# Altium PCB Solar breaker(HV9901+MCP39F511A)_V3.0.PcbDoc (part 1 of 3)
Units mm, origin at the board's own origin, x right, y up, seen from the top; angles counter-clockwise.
Board outline 92.89 x 56.75 mm, 4 copper layers (Component Side, Layer 2, Layer 3, Solder Side), stack 0.466 mm thick; 133 components, 95 nets, 366 pads, 141 vias.
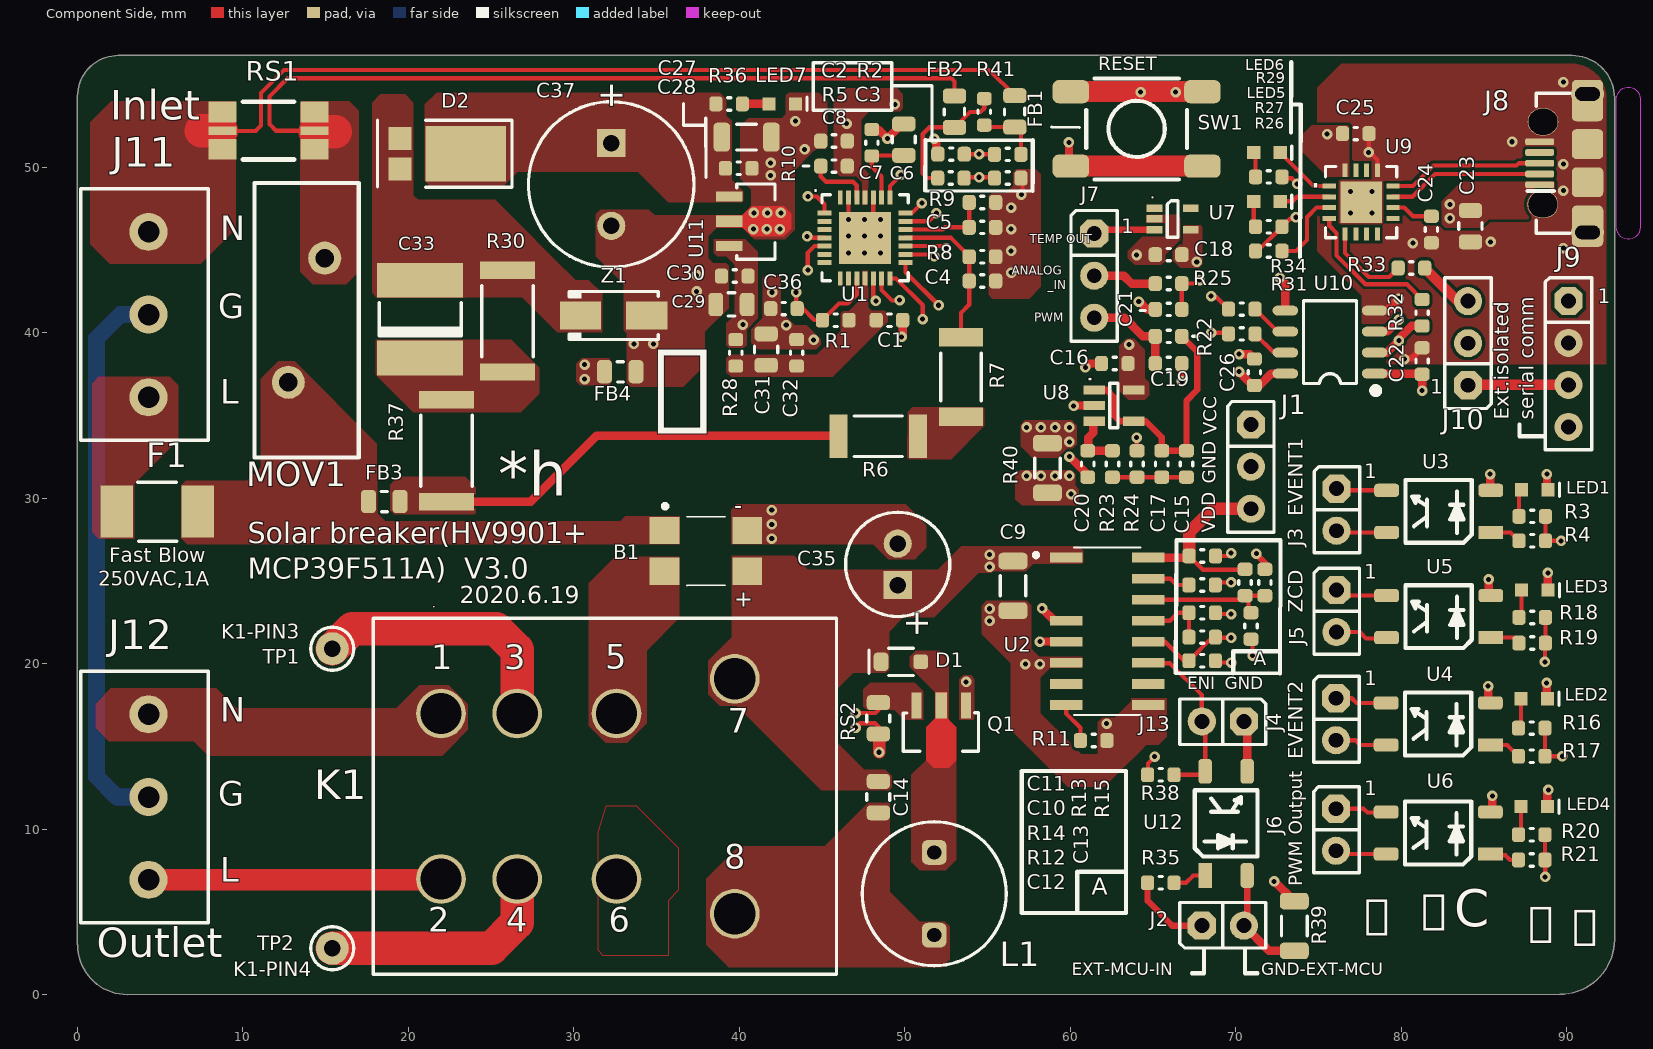
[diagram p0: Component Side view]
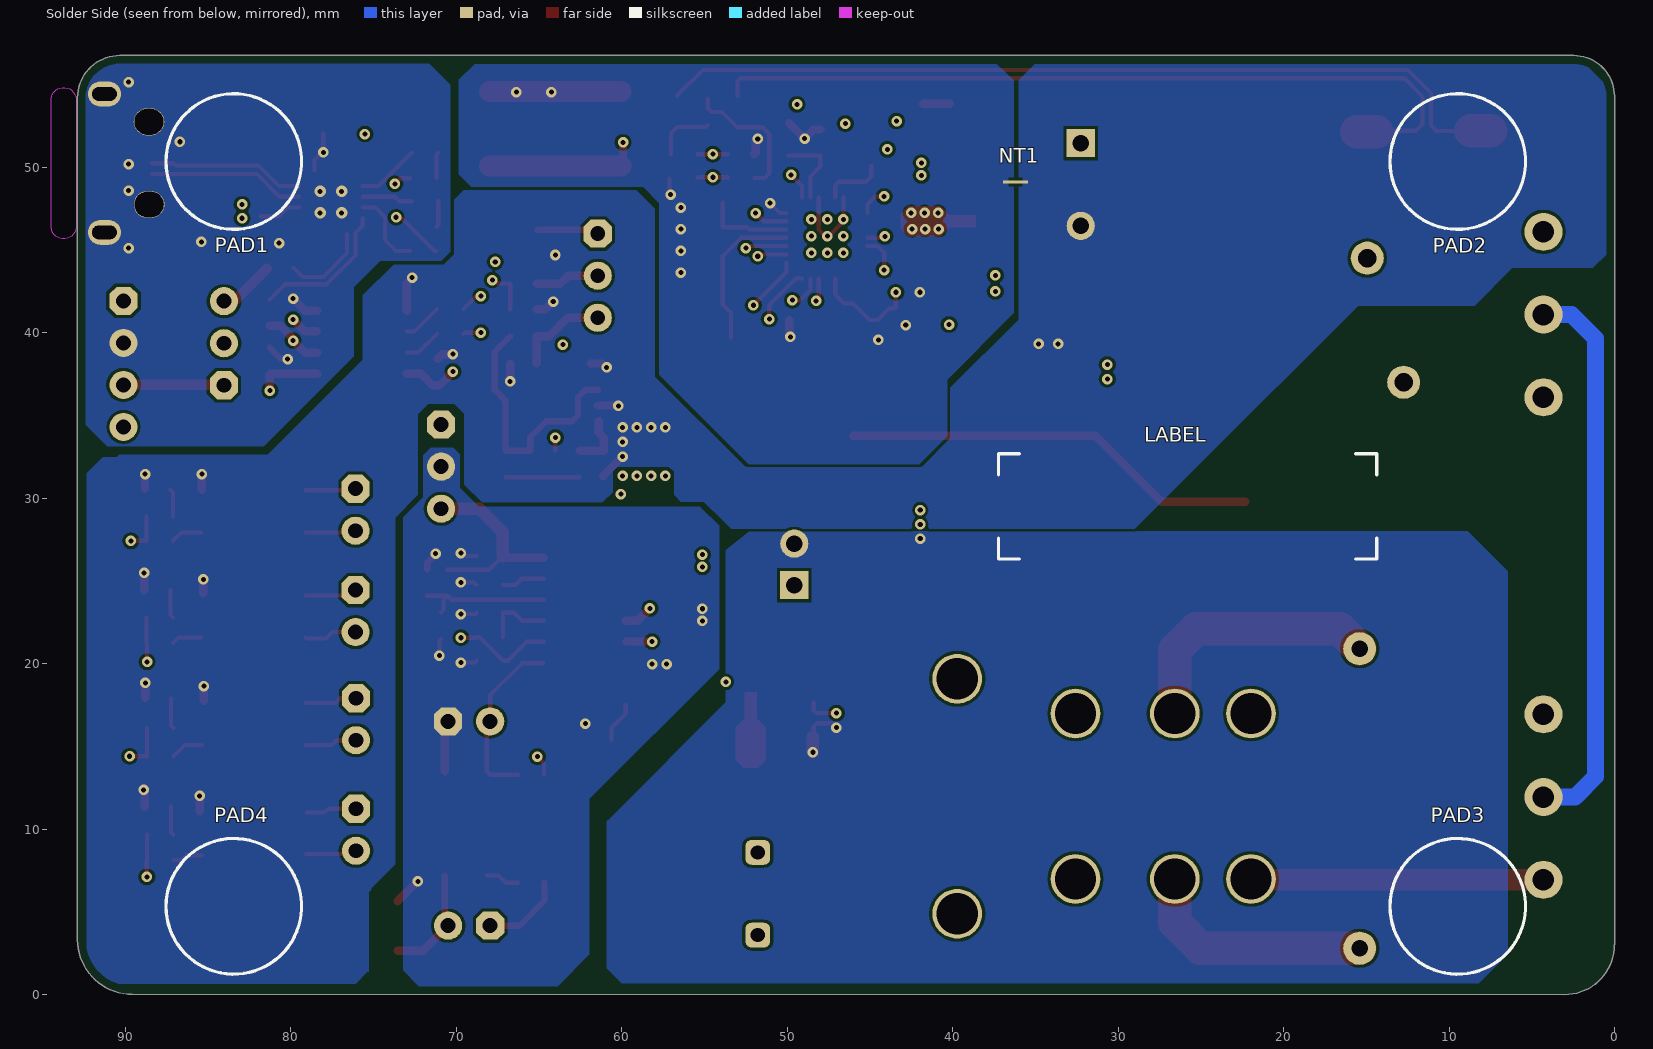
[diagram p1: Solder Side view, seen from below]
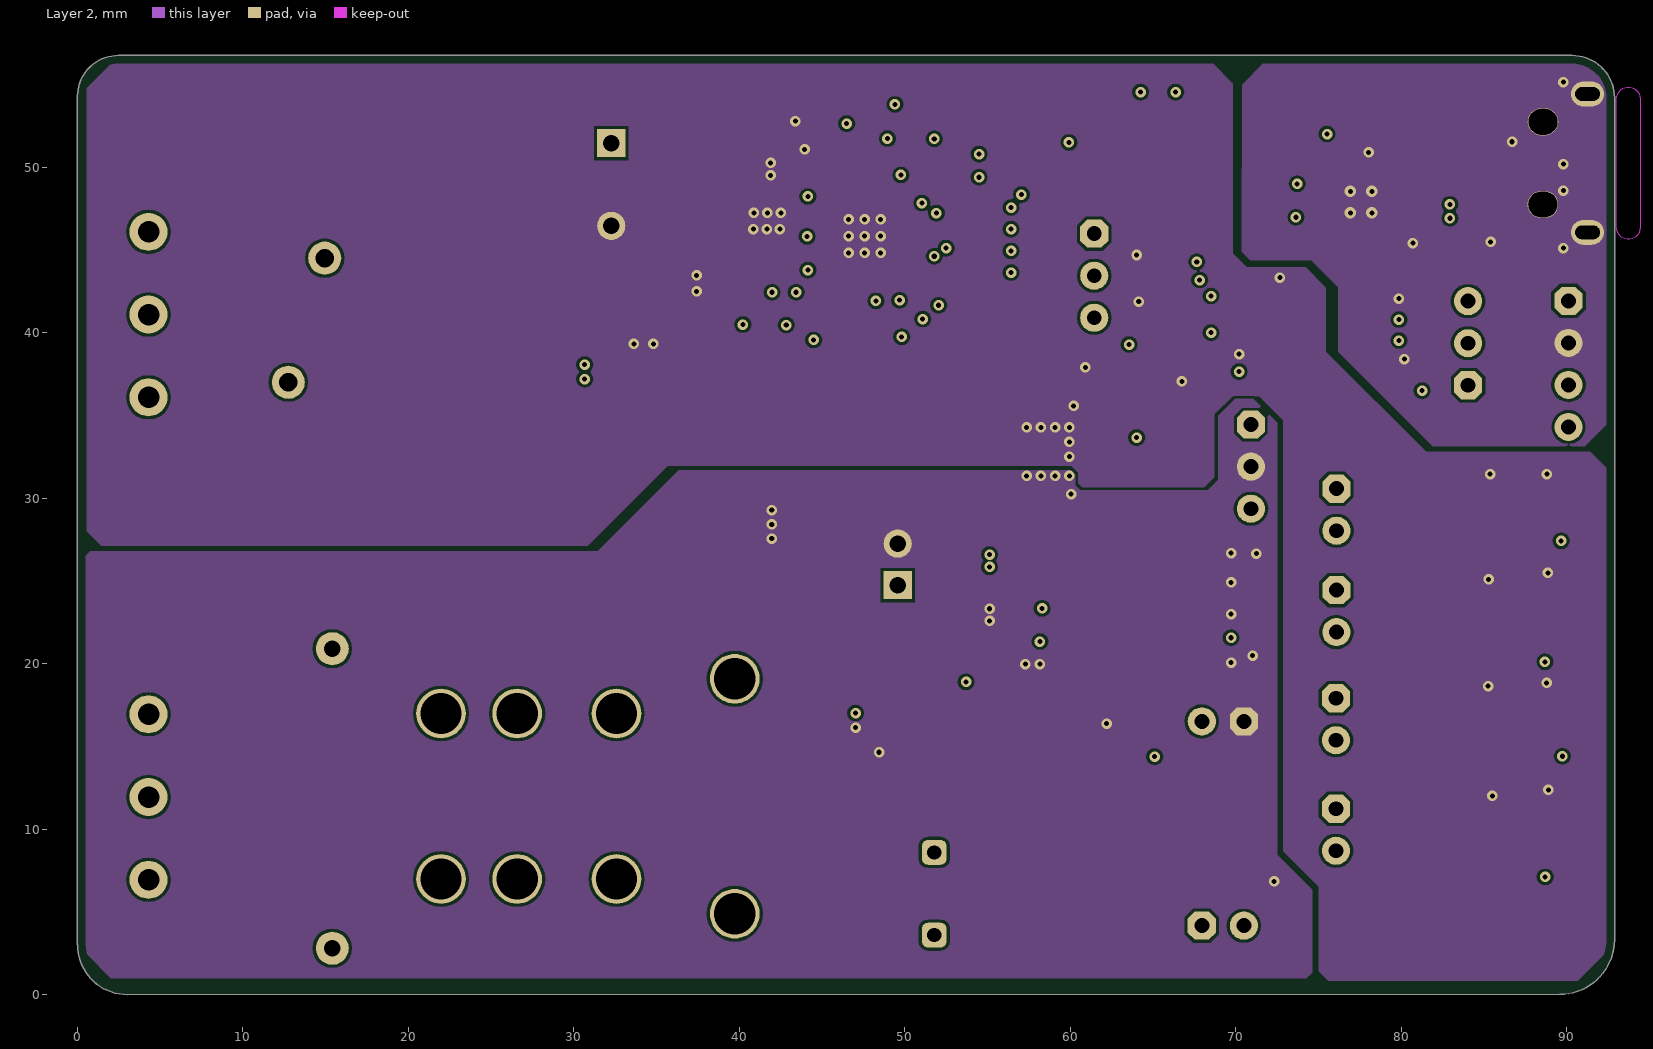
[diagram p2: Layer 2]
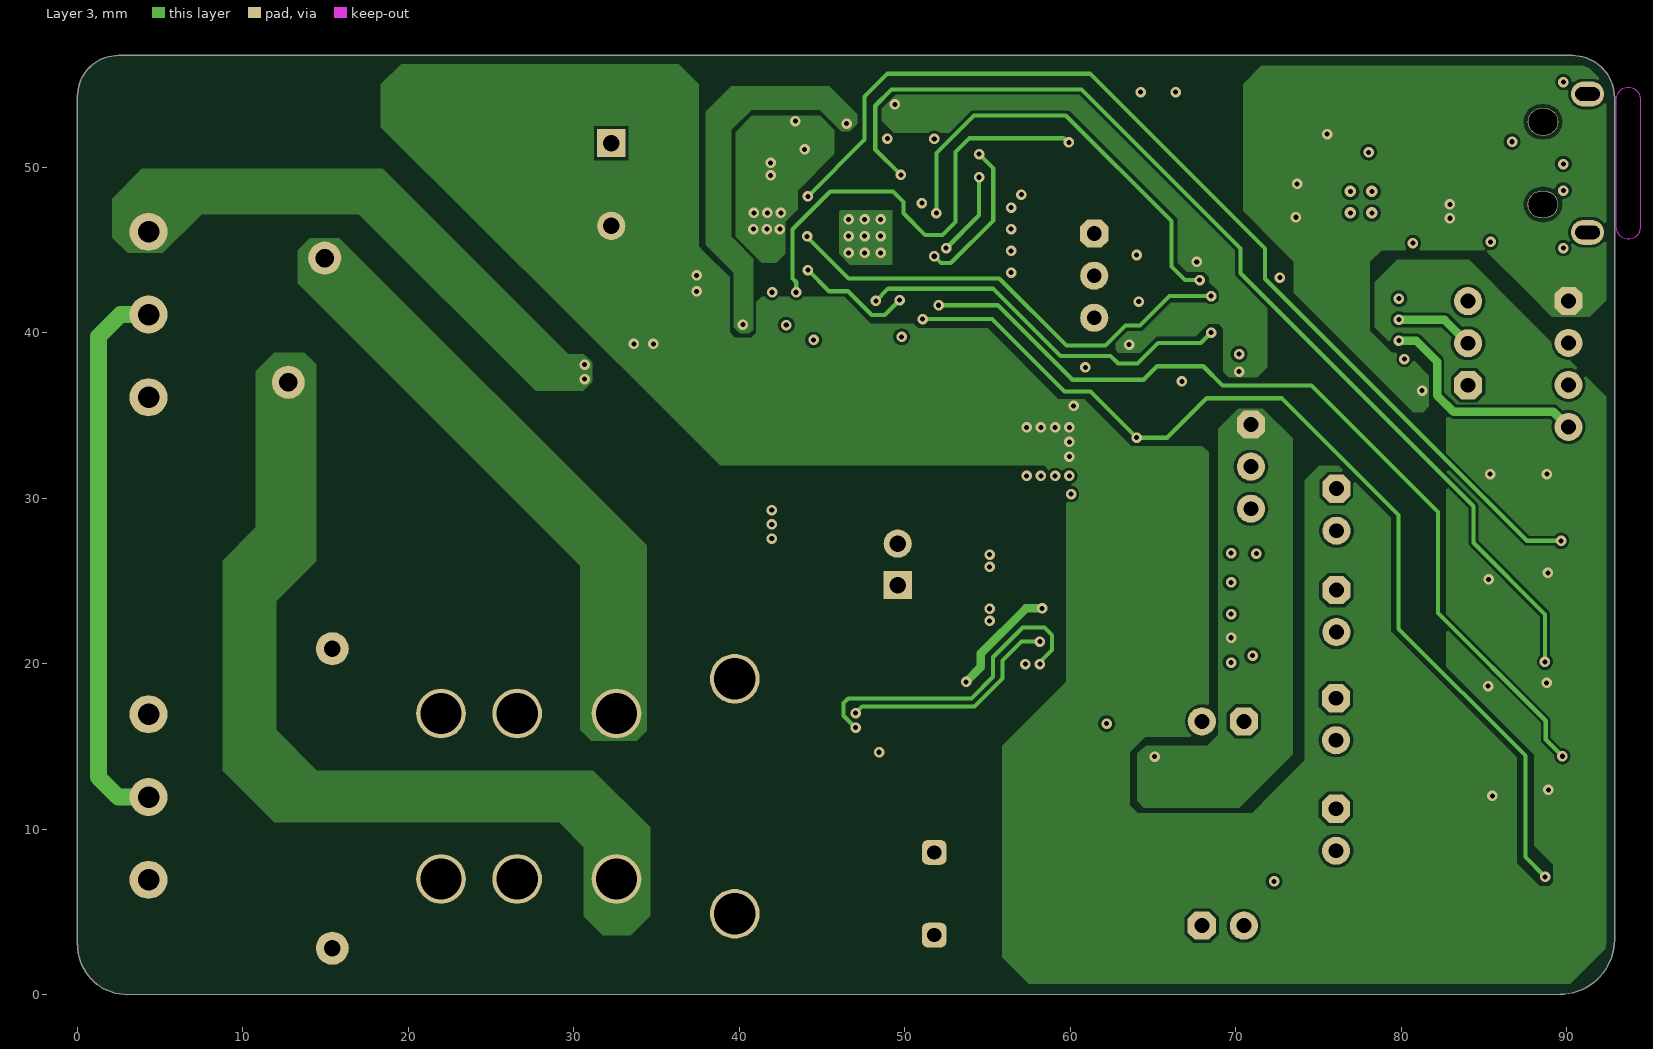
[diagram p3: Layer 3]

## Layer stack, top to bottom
Top Solder: solder mask 0.0102, Solder Resist, Dk 3.5
Component Side: signal copper 0.0635
Dielectric 3: prepreg 0.127, Dk 4.2
Layer 2: signal copper 0.035
Dielectric 2: prepreg 0.0711, PP-006, Dk 4.1
Layer 3: signal copper 0.035
Dielectric 1: prepreg 0.0711, PP-006, Dk 4.1
Solder Side: signal copper 0.0635
Bottom Solder: solder mask 0.0102, Solder Resist, Dk 3.5

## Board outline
0,3.001 0,54.282 cw(c2.471,54.282) 2.471,56.752 2.471,56.75 90.328,56.75 cw(c90.328,54.191) 92.886,54.191 92.886,3.327 cw(c89.58,3.327) 89.58,0.021 89.58,0.011 3.013,-0.001 3.013,0 cw(c3.013,3.001)

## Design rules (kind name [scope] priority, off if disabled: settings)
AcuteAngle [All] p1: minimum=9.00000000000000E+0001 checktracksonly=TRUE
BoardOutlineClearance BoardOutlineClearance_Overlay [OnLayer('Top Overlay','Bottom Overlay')] p1: gap=0.2 ignorepadtopadclearanceinfootprint=FALSE
BoardOutlineClearance [All] p2: gap=0.5 ignorepadtopadclearanceinfootprint=FALSE
Clearance "ext2/int1 OZ" [All] p1: gap=0.178 ignorepadtopadclearanceinfootprint=TRUE
ComponentClearance ComponentClearance_ignore [HasFootprint('NET_TIE_0.5mm')] p1: gap=0 collisioncheckmode=3 verticalgap=0 showdistances=FALSE
ComponentClearance [All] p2: gap=0.2 collisioncheckmode=3 verticalgap=0.2 showdistances=FALSE
DiffPairsRouting [All] p1: maxlimit=0.254 minlimit=0.25 mostfreqgap=0.254 toplayer_maxgap=0.25 toplayer_prefgap=0.25 toplayer_minwidth=0.25 toplayer_maxwidth=0.25 toplayer_prefwidth=0.25 midlayer1_mingap=0.254 midlayer1_minwidth=0.381 midlayer1_maxwidth=0.381 midlayer1_prefwidth=0.381 midlayer2_mingap=0.254 midlayer2_minwidth=0.381 midlayer2_maxwidth=0.381 midlayer2_prefwidth=0.381 bottomlayer_maxgap=0.25 bottomlayer_prefgap=0.25 bottomlayer_minwidth=0.25 bottomlayer_maxwidth=0.25 bottomlayer_prefwidth=0.25 maxuncoupledlength=12.7
FabricationTestPointUsage TestPointUsage [All] p1: valid=0 allowmultiple=FALSE
FabricationTestpoint Testpoint [All] p1: side=3 testpointundercomponent=TRUE minsize=1.016 maxsize=2.54 preferedsize=1.524 minholesize=0 maxholesize=1.016 preferedholesize=0.813 testpointgrid=0.025 allowsidetop=TRUE allowsidebottom=TRUE usegrid=TRUE gridtolerance=0
HoleSize [All] p1: absolutevalues=TRUE maxlimit=6 minlimit=0.25 maxpercent=80.000 minpercent=20.000
HoleToHoleClearance [All] p1: gap=0 allowstackedmicrovias=FALSE
MinimumAnnularRing [All] p1: minimumring=0.15
MinimumSolderMaskSliver [All] p1: minsoldermaskwidth=0
NetAntennae [All] p1: netantennaetolerance=0.003
PlaneClearance PlaneClearance_pads [IsPad] p1: clearance=0.3
PlaneClearance PlaneClearance_drill [IsObjectKind('Hole')] p2: clearance=0.4
PlaneConnect PlaneConnect_full [IsVia] p1: planeconnectstyle=Direct reliefexpansion=0.5 reliefentries=4 reliefconductorwidth=0.3 reliefairgap=0.3
PlaneConnect [All] p2: planeconnectstyle=Relief reliefexpansion=0.3 reliefentries=4 reliefconductorwidth=0.25 reliefairgap=0.25
PolygonConnect PolygonConnect_full [All vs IsVia or IsNamedPolygon('Component Side-GND_ISO')] p1 off: connectstyle=Direct reliefconductorwidth=0 reliefentries=4 polygonreliefangle="90 Angle" airgapwidth=0.254
PolygonConnect PolygonConnect_full_1 [All] p2: connectstyle=Direct reliefconductorwidth=0 reliefentries=4 polygonreliefangle="90 Angle" airgapwidth=0.254
RoutingCorners [All] p1: cornerstyle=45-Degree minsetback=2.5 maxsetback=2.5
RoutingVias [All] p1: holewidth=0.4 width=0.8 viastyle="Through Hole" minholewidth=0.3 minwidth=0.203 maxholewidth=1.6 maxwidth=2.5 viatemplateguid#1={D7C4D080-811F-470A-BF0F-E101901BD8B5} viatemplateguid#2={D88F40CF-629F-4EFE-9C57-B8998890B10F} viatemplateguid#3={0D7D6829-D953-4B47-9235-EF80532AD771} viatemplatename#1=v70h30 viatemplatename#2=v64h30 viatemplatename#3=v102h61
SMDToCorner [All] p1: distance=39370
ShortCircuit [IsNet] p1: allowed=FALSE
SilkToSilkClearance [All] p1: silktosilkclearance=0.025
SilkToSolderMaskClearance SilkscreenOverComponentPads [IsPad] p1: minsilkscreentomaskgap=0 clearancetoexposedcopper=TRUE
SolderMaskExpansion SolderMaskExpansion_Component_Via [IsComponentVia] p1: expansion=0.075 soldermaskfromhole=TRUE
SolderMaskExpansion [All] p2: expansion=0.1
UnConnectedPin [All] p1:
UnRoutedNet [All] p1: checkbadconnections=TRUE
ViasUnderSMD [All] p1: allowed=FALSE
Width Width_GND [InNet('GND')] p1: maxlimit=1.524 minlimit=0.254 preferedwidth=0.254 toplayer_maxwidth=0.508 bottomlayer_maxwidth=0.508 minimp=50.000000 maximp=50.000000 favimp=50.000000
Width Width_DEFAULT [All] p2: maxlimit=10.16 minlimit=0.203 preferedwidth=0.254 toplayer_minwidth=0.254 bottomlayer_minwidth=0.254 minimp=50.000000 maximp=50.000000 favimp=50.000000
15 further rules are at their usual default settings.

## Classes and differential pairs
component class "HV9901 Relay Driver_V3.0": B1 C9 C10 C11 C12 C13 C14 C35 D1 J1 J2 J13 K1 L1 LABEL PAD1 PAD2 PAD3 PAD4 Q1 R11 R12 R13 R14 R15 R35 R38 R39 RS2 TP1 TP2 U2 U12
component class "MCP39F511A Power Monitoring_V3.0": C1 C2 C3 C4 C5 C6 C7 C8 C15 C16 C17 C18 C19 C20 C21 C22 C23 C24 C25 C26 C27 C28 C29 C30 C31 C32 C33 C36 C37 D2 D6 F1 FB1 FB2 FB3 FB4 J3 J4 J5 J6 J7 J8 J9 J10 J11 J12 LED1 LED2 LED3 LED4 LED5 LED6 LED7 MOV1 NT1 Q5 Q? R1 R2 R3 R4 R5 R6 R7 R8 R9 R10 R16 R17 R18 R19 R20 R21 R22 R23 R24 R25 R26 R27 R28 R29 R30 R31 R32 R33 R34 R36 R37 R40 R41 R100 RS1 SW1 TP? U1 U3 U4 U5 U6 U7 U8 U9 U10 U11 Z1

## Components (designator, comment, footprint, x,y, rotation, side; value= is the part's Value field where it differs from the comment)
B1 "B?" "HD01-HD06,DIODES,BRIDGE RECTIFIER" 38.878,26 r270 top
C1 "Capacitor NP" CAP_C_0603 49.069,40.752 r180 top value=0.1uF
C2 "Capacitor NP" CAP_C_0603 52.794,50.787 r0 top value=0.033uF
C3 "Capacitor NP" CAP_C_0603 56.218,49.342 r0 top value=0.033uF
C4 "Capacitor NP" CAP_C_0603 54.687,43.122 r180 top value=0.033uF
C5 "Capacitor NP" CAP_C_0603 54.687,46.366 r180 top value=0.033uF
C6 "Capacitor NP" CAP_C_0805 49.936,51.664 r270 top value=10uF
C7 "Capacitor NP" CAP_C_0603 48.002,51.48 r270 top value=0.1uF
C8 "Capacitor NP" CAP_C_0603 45.72,51.58 r0 top value=0.1uF
C9 "Capacitor NP" CAP_C_1206 56.536,24.702 r90 top value=0.1uF
C10 "Capacitor NP" CAP_C_0603 67.964,24.75 r180 top value=0.1uF
C11 "Capacitor NP" CAP_C_0603 67.976,26.506 r0 top value=1uF
C12 "Capacitor NP" CAP_C_0603 67.965,20.175 r0 top value=0.1uF
C13 "Capacitor NP" CAP_C_0603 70.917,22.276 r90 top value=22nF
C14 "Capacitor NP" CAP_C_0805 48.396,11.934 r90 top value=0.047uF
C15 "Capacitor NP" CAP_C_0603 67.017,32.066 r90 top value=3300pF
C16 "Capacitor NP" CAP_C_0603 62.683,38.137 r0 top value=0.1uF
C17 "Capacitor NP" CAP_C_0603 65.525,32.066 r90 top value=0.01uF
C18 "Capacitor NP" CAP_C_0603 65.937,44.712 r0 top value=0.1uF
C19 "Capacitor NP" CAP_C_0603 65.937,38.137 r180 top value=0.1uF
C20 "Capacitor NP" CAP_C_0603 61.05,32.066 r90 top value=0.01uF
C21 "Capacitor NP" CAP_C_0603 65.937,41.41 r0 top value=0.1uF
C22 "Capacitor NP" CAP_C_0603 81.26,38.287 r90 top value=0.1uF
C23 "Capacitor NP" CAP_C_0805 84.179,46.434 r90 top value=4.7uF
C24 "Capacitor NP" CAP_C_0603 81.817,46.234 r270 top value=1uF
C25 "Capacitor NP" CAP_C_0603 77.25,52.026 r0 top value=0.1uF
C26 "Capacitor NP" CAP_C_0603 71.119,37.614 r90 top value=0.1uF
C27 "Capacitor NP" CAP_C_1206 40.437,51.816 r180 top value=10uF
C28 "Capacitor NP" CAP_C_0603 39.956,49.935 r180 top value=0.1uF
C29 "Capacitor NP" CAP_C_0805 39.522,41.703 r0 top value=10uF
C30 "Capacitor NP" CAP_C_0603 39.722,43.419 r0 top value=0.1uF
C31 "Capacitor NP" CAP_C_0805 41.619,38.98 r270 top value=10uF
C32 "Capacitor NP" CAP_C_0603 43.463,38.78 r270 top value=0.1uF
C33 "Capacitor NP" CAP_C_2220_Stack-2 20.709,40.818 r90 top value=1uF
C35 "Capacitor POL" CAP_RAD_P2.5D6.3H11.2 49.569,26 r90 top value=1uF
C36 "Capacitor NP" CAP_C_0603 42.691,41.453 r0 top value=0.1uF
C37 "Capacitor POL" CAP_RAD_P5D10H20 32.258,48.956 r270 top locked value=470uF
D1 "Diode Single" SC-90A 49.759,20.112 r0 top value=RFU02VSM8STR
D2 "PowerDI5_Diode" PowerDI5_Diode 23.469,50.82 r90 top
F1 "Fuse_476 series fuse (Littelfuse)_2410" "Fuse_476 series fuse (Littelfuse)_2410" 4.826,29.202 r180 top
FB1 "Ferrite Bead" IND_C_0805 56.645,53.372 r270 top value=150R
FB2 "Ferrite Bead" IND_C_0805 53.001,53.354 r270 top value=150R
FB3 "Ferrite Bead" IND_C_0805 18.537,29.8 r0 top value=150R
FB4 "Ferrite Bead" IND_C_0805 32.8,37.643 r0 top value=150R
J1 "Header 1x3" HDR_M_2.54_1x3 70.909,31.902 r270 top value="HDR-2.54 Male 1x3"
J2 "Header 1x2" HDR_M_2.54_1x2 69.215,4.166 r0 top value="HDR-2.54 Male 1x2"
J3 "Header 1x2" HDR_M_2.54_1x2 76.081,29.302 r270 top value="HDR-2.54 Male 1x2"
J4 "Header 1x2" HDR_M_2.54_1x2 76.052,16.641 r270 top value="HDR-2.54 Male 1x2"
J5 "Header 1x2" HDR_M_2.54_1x2 76.079,23.173 r270 top value="HDR-2.54 Male 1x2"
J6 "Header 1x2" HDR_M_2.54_1x2 76.052,9.961 r270 top value="HDR-2.54 Male 1x2"
J7 "Header 1x3" HDR_M_2.54_1x3 61.443,43.442 r270 top value="HDR-2.54 Male 1x3"
J8 "USB2.0 Micro-B female connector-compatible with 629105150921,629105136821,C8359-05ZFDXNBNR" "USB2.0 Micro-B female connector-compatible with 629105150921,629105136821,C8359-05ZFDXNBNR" 91.251,50.241 r270 top value="USB2.0 MICRO-B FEMALE"
J9 "Header 1x4" HDR_M_2.54_1x4 90.104,38.113 r270 top value="HDR-2.54 Male 1x4"
J10 "Header 1x3" HDR_M_2.54_1x3 84.033,39.363 r90 top value="HDR-2.54 Male 1x3"
J11 "Header 1x1" CON_TERMINAL_5_1x3_TH_RA_WE_691137710003 4.294,41.092 r270 top value="TERMINAL 1x3"
J12 "Header 1x1" CON_TERMINAL_5_1x3_TH_RA_WE_691137710003 4.294,11.938 r270 top value="TERMINAL 1x3"
J13 "Header 1x2" HDR_M_2.54_1x2 69.215,16.51 r180 top value="HDR-2.54 Male 1x2"
K1 "RELAY_LY2-0-DC48_DPDT 10A 48V,2Poles,THD" "RELAY_LY2-0-DC48_DPDT 10A 48V,2Poles,THD" 31.872,11.985 r90 top locked
L1 "Inductor" IND_WE-TI-8055_P5D8.5H5.5 51.777,6.094 r270 top value=100mH,20mA,235ohm
LABEL "LABEL_Need_Help_Small" LABEL_Need_Help_Small 25.8,29.5 r0 bottom value="LABEL Need Help Small"
LED1 "LED_red" LED_0603_RED 88.061,30.502 r0 top value=RED
LED2 "LED_red" LED_0603_RED 88.032,17.88 r0 top value=RED
LED3 "LED_red" LED_0603_RED 88.059,24.443 r0 top value=RED
LED4 "LED_red" LED_0603_RED 88.032,11.361 r0 top value=RED
LED5 "LED_red" LED_0603_RED 71.879,47.922 r0 top value=RED
LED6 "LED_green" LED_0603_GREEN 71.879,50.886 r0 top value=Green
LED7 "LED_red" LED_0603_RED 42.591,53.824 r0 top value=RED
MOV1 "Varistor" MOV_EPC_S14KXX 13.843,40.753 r270 top value=275V
NT1 "Net Tie" NET_TIE_0.2mm 36.2,49.1 r180 bottom net-tie
PAD1 "Rubber Pad Cylindrical" BUMP_3M_SJ61A11_CYLINDRICAL_BLACK_D7.9H5.3 83.439,50.343 r180 bottom value="Rubber Pad Cyl D7.9H5.3"
PAD2 "Rubber Pad Cylindrical" BUMP_3M_SJ61A11_CYLINDRICAL_BLACK_D7.9H5.3 9.474,50.343 r180 bottom value="Rubber Pad Cyl D7.9H5.3"
PAD3 "Rubber Pad Cylindrical" BUMP_3M_SJ61A11_CYLINDRICAL_BLACK_D7.9H5.3 9.474,5.334 r180 bottom value="Rubber Pad Cyl D7.9H5.3"
PAD4 "Rubber Pad Cylindrical" BUMP_3M_SJ61A11_CYLINDRICAL_BLACK_D7.9H5.3 83.439,5.334 r180 bottom value="Rubber Pad Cyl D7.9H5.3"
Q1 "Transistor MOS-N GDS" SOT-89-3 52.197,15.72 r180 top value=VN2460N8-G
R1 "Resistor" RES_C_0603 45.818,40.752 r0 top value=4.7k
R2 "Resistor" RES_C_0603 56.218,50.775 r0 top value=1k
R3 "Resistor" RES_C_0603 87.911,28.902 r0 top value=1k
R4 "Resistor" RES_C_0603 87.911,27.424 r0 top value=1k
R5 "Resistor" RES_C_0603 52.781,49.342 r180 top value=1k
R6 "Resistor" RES_C_2010 48.396,33.744 r0 top value=499k
R7 "Resistor" RES_C_2010 53.399,37.323 r90 top value=499k
R8 "Resistor" RES_C_0603 54.687,44.588 r180 top value=1k
R9 "Resistor" RES_C_0603 54.687,47.87 r180 top value=1k
R10 "Resistor" RES_C_0603 45.72,50.064 r180 top value=4.7k
R11 "Resistor" RES_C_0603 61.408,15.353 r180 top value=470k
R12 "Resistor" RES_C_0603 67.964,21.601 r0 top value=30k
R13 "Resistor" RES_C_0603 70.56,24.904 r90 top value=180k
R14 "Resistor" RES_C_0603 67.964,23.074 r180 top value=10k
R15 "Resistor" RES_C_0603 71.755,24.904 r270 top value=10k
R16 "Resistor" RES_C_0603 87.882,16.102 r0 top value=1k
R17 "Resistor" RES_C_0603 87.882,14.402 r0 top value=1k
R18 "Resistor" RES_C_0603 87.909,22.793 r0 top value=1k
R19 "Resistor" RES_C_0603 87.909,21.243 r0 top value=1k
R20 "Resistor" RES_C_0603 87.882,9.661 r0 top value=1k
R21 "Resistor" RES_C_0603 87.882,8.137 r0 top value=1k
R22 "Resistor" RES_C_0603 65.937,39.776 r180 top value=1k
R23 "Resistor" RES_C_0603 62.541,32.066 r90 top value=100K
R24 "Resistor" RES_C_0603 64.033,32.066 r270 top value=100K
R25 "Resistor" RES_C_0603 65.937,42.966 r0 top value=100R
R26 "Resistor" RES_C_0603 71.987,44.933 r180 top value=10k
R27 "Resistor" RES_C_0603 71.987,46.403 r0 top value=1k
R28 "Resistor" RES_C_0603 39.781,38.78 r90 top value=33R
R29 "Resistor" RES_C_0603 71.995,49.418 r0 top value=1k
R30 "Resistor" RES_C_2512 25.989,40.7 r270 top value=1M
R31 "Resistor" RES_C_0603 70.357,39.928 r0 top value=100R
R32 "Resistor" RES_C_0603 81.26,41.208 r90 top value=100R
R33 "Resistor" RES_C_0603 80.61,43.91 r180 top value=100R
R34 "Resistor" RES_C_0603 70.357,41.424 r0 top value=100R
R35 "Resistor" RES_C_0603 65.468,6.756 r0 top value=1k
R36 "Resistor" RES_C_0603 39.381,53.824 r180 top value=1k
R37 "Resistor" RES_C_2512 22.3,32.866 r270 top value=120R
R38 "Resistor" RES_C_0603 65.468,13.284 r180 top value=10k
R39 "Resistor" RES_C_1206 73.533,4.147 r90 top value=0R
R40 "Resistor" RES_C_1206 58.618,31.82 r90 top value=0R
R41 "Resistor" RES_C_0603 54.8,53.342 r90 top value=2.49R
RS1 "Shunt 4 Pin" RES_C_2512_SHUNT 11.544,52.206 r180 top value=0.002R
RS2 "Resistor" RES_C_0805 48.396,16.695 r90 top value=39R
SW1 "Switch 4 Pin" SW_TACT_SMD_B3S-1000 64.008,52.313 r180 top value=430182043816
TP1 "Test Point" CON_TP_TH_V_WHT_KEC_5002 15.4,20.9 r90 top value="TP LOOP White"
TP2 "Test Point" CON_TP_TH_V_WHT_KEC_5002 15.4,2.8 r90 top value="TP LOOP White"
U1 "MCP39F511 QFN-28" QFN-28_5x5 47.596,45.731 r0 top locked value=MCP39F511AT-E/MQ
U2 "HV9901NG-G-M901" *SOIC127P600X175-14N 62.222,21.956 r0 top locked
U3 "Photocoupler Transistor Out" 4-SMD_200mil 82.261,29.202 r180 top value=HCPL-181-06AE
U4 "Photocoupler Transistor Out" 4-SMD_200mil 82.231,16.356 r180 top value=HCPL-181-06AE
U5 "Photocoupler Transistor Out" 4-SMD_200mil 82.259,22.842 r180 top value=HCPL-181-06AE
U6 "Photocoupler Transistor Out" 4-SMD_200mil 82.231,9.761 r180 top value=HCPL-181-06AE
U7 "MCP9700(A)_1(A) SC-70-5" SC-70-5 66.183,46.871 r270 top value=MCP9700T-H/LT
U8 "MCP6XX1_6 SOT-23-5_SC-70-5" SOT-23-5 62.634,35.597 r270 top value=MCP6021T-E/OT
U9 "MCP2221 QFN-16" QFN-16_4X4_EP2.5X2.5 77.575,47.886 r0 top value=MCP2221AT-I/ML
U10 "FOD8012" SOIC-8 75.692,39.429 r180 top value=FOD8012AR2
U11 "MCP1754S SOT-89-3_SOT-223-3" SOT-89-3 41.141,46.734 r270 top value=MCP1754ST-3302E/MB
U12 "Photocoupler Transistor Out" 4-SMD_200mil 69.418,10.344 r90 top value=HCPL-181-06AE
Z1 "Diode Zener" DO-214AC_SMA 32.4,41.042 r180 top value=5.6V

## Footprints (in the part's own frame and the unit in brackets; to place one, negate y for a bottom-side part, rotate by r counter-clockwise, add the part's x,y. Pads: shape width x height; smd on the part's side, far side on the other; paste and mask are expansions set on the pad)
4-SMD_200mil [mm] "Photocoupler PC365N Darlington Output 4-SMD"
  rect 1.5x0.8 smd: 1(-3.15,1.27)
  rrect50% 1.5x0.8 smd: 2(-3.15,-1.27) 3(3.15,-1.27) 4(3.15,1.27)
  silkscreen extent -2,-1.9 2,1.9, body extent -3.45,-1.8 3.55,1.8, height 2.1
*SOIC127P600X175-14N [mm]
  rect 1.97x0.6 smd: 1(-2.475,4.445) 4(-2.475,0.635) 5(-2.475,-0.635) 6(-2.475,-1.905) 7(-2.475,-3.175) 8(-2.475,-4.445) 9(2.475,-4.445) 10(2.475,-3.175) 11(2.475,-1.905) 12(2.475,-0.635) 13(2.475,0.635) 14(2.475,1.905) 15(2.475,3.175) 16(2.475,4.445)
  silkscreen extent -4.4,-5.06 2,5.06
BUMP_3M_SJ61A11_CYLINDRICAL_BLACK_D7.9H5.3 [mm] "3M Bumpon Cylindrical D=7.9mm, H5.3mm"
  silkscreen extent -4.1,-4.1 4.1,4.1, body extent -3.97,-3.97 3.97,3.97, height 5.33
CAP_C_0603 [mm] "Chip Capacitor, 2-Leads, Body 1.6x0.8mm, IPC Medium Density"
  rrect50% 0.8x0.9 smd: 1(-0.8,0) 2(0.8,0)
  silkscreen extent -0.1,-0.38 0.1,0.38, body extent -0.8,-0.4 0.8,0.4, height 0.3
CAP_C_0805 [mm] "Chip Capacitor, 2-Leads, Body 2.0x1.3mm, IPC Medium Density"
  rrect50% 0.9x1.4 smd: 1(-0.95,0) 2(0.95,0)
  silkscreen extent -0.2,-0.7 0.2,0.7, body extent -1,-0.62 1,0.63, height 0.78
CAP_C_1206 [mm] "Chip Capacitor, 2-Leads, Body 3.2x1.6mm, IPC Medium Density"
  rrect50% 1x1.75 smd: 1(-1.5,0) 2(1.5,0)
  silkscreen extent -0.6,-0.77 0.6,0.77, body extent -1.6,-0.8 1.6,0.8, height 1
CAP_C_2220_Stack-2 [mm] "Chip Capacitor, 2-Leads, Body 5.7x5.0mm, Stacked-2"
  rect 2.1x5.2 smd: 1(-2.35,0) 2(2.35,0)
  silkscreen extent -1,-2.47 1,2.48, body extent -3.05,-2.54 3.05,2.54, height 5
CAP_RAD_P2.5D6.3H11.2 [mm] "Capacitor, Electrolytic, Radial; Body P=2.5mm, D=6.3mm, H=11.2mm"
  rect 1.7x1.7 hole 1: 1(-1.25,0)
  round 1.7 hole 1: 2(1.25,0)
  silkscreen extent -3.15,-3.15 3.15,3.15, body extent -3.12,-3.14 3.15,3.14, height 11.2
CAP_RAD_P5D10H20 [mm] "Capacitor, Electrolytic, Radial; Body P=5mm, D=10mm, H=20mm"
  rect 1.7x1.7 hole 1: 1(-2.5,0)
  round 1.7 hole 1: 2(2.5,0)
  silkscreen extent -5,-5 5,5, body extent -5,-4.99 5,5, height 20
CON_TERMINAL_5_1x3_TH_RA_WE_691137710003 [mm]
  round 2.3 hole 1.3: 1(-5,0) 2(0,0) 3(5,0)
  silkscreen extent -7.6,-4.1 7.6,3.6, body extent -7.5,-4 7.5,3.5, height 11.5
CON_TP_TH_V_WHT_KEC_5002 [mm] "TEST POINT PC MULTI PURPOSE MINI WHT"
  round 2 hole 1: 1(0,0)
  silkscreen extent -1.3,-1.3 1.3,1.3, body extent -1.27,-1.27 1.27,1.27, height 4.89
DO-214AC_SMA [mm] "Molded Diode, 2-Leads, Body 5.0x2.7mm, IPC Medium Density"
  rect 2.5x1.7 smd: 1(-2,0) 2(2,0)
  silkscreen extent -2.7,-1.5 2.7,1.5, body extent -2.6,-1.3 2.6,1.3, height 2.4
"Fuse_476 series fuse (Littelfuse)_2410" [mm] "Fuse_476 series fuse (Littelfuse)_2410, Body 6.1X2.69X2.69mm"
  rect 1.955x3.15 smd paste-0.051: 1(-2.452,0) 2(2.452,0)
  silkscreen extent -1.19,-1.75 1.19,1.8
"HD01-HD06,DIODES,BRIDGE RECTIFIER" [mm] "HD01-HD06,Diodes,bridge rectifier"
  rect 1.65x1.8 smd: 1(-2.045,-3.4) 2(0.425,-3.4) 3(0.425,1.6) 4(-2.045,1.6)
  silkscreen extent -3.62,-3.48 1.27,0.25, body extent -3.33,-4.21 1.82,2.39, height 1.6
HDR_M_2.54_1x2 [mm] "Header Male Vertical 4 Way 2.54mm Pitch"
  oct 1.7x1.7 hole 0.9: 1(-1.27,0)
  round 1.7 hole 0.9: 2(1.27,0)
  silkscreen extent -2.6,-1.35 2.6,1.4, body extent -2.54,-1.27 2.54,1.27, height 5.94
HDR_M_2.54_1x3 [mm] "Header Male Vertical 4 Way P=2.54mm"
  oct 1.7x1.7 hole 0.9: 1(-2.54,0)
  round 1.7 hole 0.9: 2(0,0) 3(2.54,0)
  silkscreen extent -3.94,-1.4 3.96,1.4, body extent -3.8,-1.26 3.82,1.28, height 5.94
HDR_M_2.54_1x4 [mm] "Header Male Vertical 4 Way 2.54mm Pitch"
  oct 1.7x1.7 hole 0.9: 1(-3.81,0)
  round 1.7 hole 0.9: 2(-1.27,0) 3(1.27,0) 4(3.81,0)
  silkscreen extent -5.21,-1.4 5.19,1.4, body extent -5.08,-1.27 5.08,1.27, height 5.94
IND_C_0805 [mm] "Chip Inductor, 2-Leads, Body 2.0x1.3mm, IPC Medium Density"
  rrect50% 0.9x1.4 smd: 1(-0.95,0) 2(0.95,0)
  silkscreen extent -0.2,-0.63 0.2,0.6, body extent -1,-0.6 1,0.6, height 0.95
IND_WE-TI-8055_P5D8.5H5.5 [mm] "WE-TI Radial Leaded Wire Wound Inductor"
  rrect50% 1.5x1.5 hole 0.85: 1(-2.5,0) 2(2.5,0)
  silkscreen extent -4.35,-4.35 4.35,4.35, body extent -5.87,-5.87 5.87,5.87, height 5.5
LABEL_Need_Help_Small [mm] "Small Serial Number Assembly Label"
  silkscreen extent -11.43,-3.17 11.43,3.17, body extent -11.43,-3.17 11.43,3.17, height 0.3
LED_0603_GREEN [mm] "LED chip 0603"
  rect 0.8x0.8 smd: 1(-0.8,0) 2(0.8,0)
  silkscreen extent 1.5,-0.4 1.5,0.4, body extent -0.81,-0.4 0.81,0.4, height 0.6
LED_0603_RED [mm] "LED chip 0603"
  rect 0.8x0.8 smd: 1(-0.8,0) 2(0.8,0)
  silkscreen extent 1.5,-0.4 1.5,0.4, body extent -0.81,-0.4 0.81,0.4, height 0.6
MOV_EPC_S14KXX [mm] "EPCOS 14mm Disc Varistor"
  round 2 hole 1.1: 1(-3.75,1.1) 2(3.75,-1.1)
  silkscreen extent -8.3,-3.15 8.3,3.15, body extent -8.51,-2.83 8.48,2.77, height 20
NET_TIE_0.2mm [mm]
  rect 0.5x0.2 smd paste-1: 0(0,0) 1(-0.5,0) 2(0.5,0)
PowerDI5_Diode [mm] "PowerDI5_Diode"
  rect 1.39x1.4 smd: 1(0.92,3.982) 2(-0.92,3.982)
  rect 3.36x4.86 smd: 3(0,0)
  silkscreen extent -2.02,-2.79 2.03,5.33, body extent -2.35,-2.86 2.4,3.79, height 1.2
QFN-16_4X4_EP2.5X2.5 [mm]
  rect 0.8x0.3 smd mask+0.075: 1(-1.925,0.975) 2(-1.925,0.325) 3(-1.925,-0.325) 4(-1.925,-0.975) 9(1.925,-0.975) 10(1.925,-0.325) 11(1.925,0.325) 12(1.925,0.975)
  rect 0.3x0.8 smd mask+0.075: 5(-0.975,-1.925) 6(-0.325,-1.925) 7(0.325,-1.925) 8(0.975,-1.925) 13(0.975,1.925) 14(0.325,1.925) 15(-0.325,1.925) 16(-0.975,1.925)
  rect 2.5x2.5 smd mask+0.075: 17(0,0)
  silkscreen extent -2.15,-2.15 2.15,2.15, body extent -2.05,-2.05 2.05,2.05, height 0.9
QFN-28_5x5 [mm] "QFN, 28-Leads, Body 5x5mm (max), Pitch 0.5mm, IPC Medium Density"
  rect 0.85x0.3 smd mask+0.05: 1(-2.45,1.5) 2(-2.45,1) 3(-2.45,0.5) 4(-2.45,0) 5(-2.45,-0.5) 6(-2.45,-1) 7(-2.45,-1.5) 15(2.45,-1.5) 16(2.45,-1) 17(2.45,-0.5) 18(2.45,0) 19(2.45,0.5) 20(2.45,1) 21(2.45,1.5)
  rect 0.3x0.85 smd mask+0.05: 8(-1.5,-2.45) 9(-1,-2.45) 10(-0.5,-2.45) 11(0,-2.45) 12(0.5,-2.45) 13(1,-2.45) 14(1.5,-2.45) 22(1.5,2.45) 23(1,2.45) 24(0.5,2.45) 25(0,2.45) 26(-0.5,2.45) 27(-1,2.45) 28(-1.5,2.45)
  rect 3.15x3.15 smd paste-2 mask+0.075: 29(0,0)
  silkscreen extent -2.6,-2.6 2.6,2.6, body extent -2.52,-2.52 2.52,2.52, height 0.9
"RELAY_LY2-0-DC48_DPDT 10A 48V,2Poles,THD" [mm] "RELAY_LY2-0-DC48_DPDT 10A 48V,2Poles,THD"
  round 3 hole 2.5: 1(5,9.9) 2(-5,9.9) 3(5,5.3) 4(-5,5.3) 5(5,-0.7) 6(-5,-0.7) 7(7.1,-7.85) 8(-7.1,-7.85)
  silkscreen extent -10.75,-14 10.75,14, body extent -5,-3.4 5,3.1, height 5
RES_C_0603 [mm] "Chip Resistor, 2-Leads, Body 1.6x0.8mm, IPC Medium Density"
  rrect50% 0.8x0.9 smd: 1(-0.8,0) 2(0.8,0)
  silkscreen extent -0.1,-0.38 0.1,0.38, body extent -0.8,-0.4 0.8,0.4, height 0.3
RES_C_0805 [mm] "Chip Resistor, 2-Leads, Body 2.0x1.3mm, IPC Medium Density"
  rrect50% 0.9x1.4 smd: 1(-0.95,0) 2(0.95,0)
  silkscreen extent -0.2,-0.7 0.2,0.7, body extent -1,-0.63 1,0.63, height 0.78
RES_C_1206 [mm] "Chip Resistor, 2-Leads, Body 3.2x1.6mm, IPC Medium Density"
  rrect50% 1x1.75 smd: 1(-1.5,0) 2(1.5,0)
  silkscreen extent -0.6,-0.77 0.6,0.78, body extent -1.6,-0.8 1.6,0.8, height 1
RES_C_2010 [mm] "Chip Resistor, 2-Leads, Body 5.0x2.5mm, IPC Medium Density"
  rect 1.1x2.65 smd: 1(-2.4,0) 2(2.4,0)
  silkscreen extent -1.45,-1.22 1.45,1.23, body extent -2.5,-1.25 2.5,1.25, height 0.65
RES_C_2512 [mm] "Chip Resistor, 2-Leads, Body 6.3x3.1mm, IPC Medium Density"
  rect 1.05x3.3 smd: 1(-3.075,0) 2(3.075,0)
  silkscreen extent -2.15,-1.55 2.15,1.55, body extent -3.17,-1.5 3.18,1.5, height 1.6
RES_C_2512_SHUNT [mm] "Metal Foil Current Sensing Chip Resistor, 2-Leads, Body 6.35x3.18mm, IPC Medium Density"
  rect 1.7x1.25 smd: 1(-2.775,-1.125) 1(-2.775,1.125) 2(2.775,-1.125) 2(2.775,1.125)
  rect 1.7x0.5 smd: 3(-2.775,0) 4(2.775,0)
  silkscreen extent -1.55,-1.75 1.55,1.75, body extent -3.17,-1.5 3.18,1.5, height 1.6
SC-70-5 [mm]
  rect 0.45x0.95 smd mask+0.05: 1(-0.65,-1.1) 2(0,-1.1) 3(0.65,-1.1) 4(0.65,1.1) 5(-0.65,1.1)
  silkscreen extent -1.1,-0.33 1.1,0.33, body extent -1,-1.05 1,1.05, height 0.95
SC-90A [mm] "Diode, 2-Leads, Body 1.8x1.35mm"
  rrect50% 0.9x0.9 smd: 1(1.2,0)
  rrect50% 0.9x1.1 smd: 2(-1.2,0)
  silkscreen extent -1.92,-0.82 0.75,0.82, body extent -0.9,-0.67 0.9,0.67, height 0.8
SOIC-8 [mm] "SOIC, 8-Leads, Overall 4.9x6mm, Pitch 1.27mm, IPC Medium Density"
  oval 1.55x0.6 smd: 1(-2.7,1.905) 2(-2.7,0.635) 3(-2.7,-0.635) 4(-2.7,-1.905) 5(2.7,-1.905) 6(2.7,-0.635) 7(2.7,0.635) 8(2.7,1.905)
  silkscreen extent -1.6,-2.5 1.6,2.5, body extent -3.01,-2.5 3.01,2.5, height 1.75
SOT-23-5 [mm] "SOT-23-5"
  rect 0.55x1.3 smd: 1(-0.95,-1.2) 2(0,-1.2) 3(0.95,-1.2) 4(0.95,1.2) 5(-0.95,1.2)
  silkscreen extent -1.35,-0.25 1.35,0.25, body extent -1.5,-1.25 1.5,1.25, height 1.08
SOT-89-3 [mm] "SOT-89-3, 4-Leads, Body 4.6x2.6mm (max), Pitch 1.5mm"
  rect 0.6x1.6 smd: 1(-1.5,-1.75) 3(1.5,-1.75)
  rect 0.7x1.6 smd: 2(0,-1.75)
  Component Side region: 0.35,-2.55 0.35,-0.975 0.355,-0.975 0.9,-0.43 0.9,1.55 0.45,2 -0.45,2 -0.9,1.55 -0.9,-0.43 -0.895,-0.43 -0.35,-0.975 -0.35,-2.55
  silkscreen extent -2.25,-1.31 2.3,1.02, body extent -2.25,-2.25 2.25,1.75, height 1.5
SW_TACT_SMD_B3S-1000 [mm] "Switch Tact B3S-1000 / B3S-1002 L=6mm W=6.6mm H=4.3mm"
  rrect50% 2.2x1.4 smd: 1(3.975,-2.25) 2(-3.975,-2.25) 3(3.975,2.25) 4(-3.975,2.25)
  silkscreen extent -3.05,-3.05 3.05,3.05, body extent -4.5,-3 4.5,3, height 5
"USB2.0 Micro-B female connector-compatible with 629105150921,629105136821,C8359-05ZFDXNBNR" [mm] "USB2.0 Micro-B female connector-compatible with 629105150921,629105136821,C8359-05ZFDXNBNR"
  rrect30% 2.5x1.9 smd paste-0.051: 0(-3.785,0) 0(3.802,0.005)
  rrect30% 1.8x1.9 smd paste-0.051: 0(-1.153,0) 0(1.151,0.005)
  rrect50% 0.4x1.75 smd paste-0.046 mask+0.05: 1(1.3,-2.888) 2(0.65,-2.888) 3(0,-2.888) 4(-0.65,-2.888) 5(-1.3,-2.888)
  oval 1.5x2 hole 0.825 slot 1.5 at 90 deg paste+0 mask+0.102: ""(-4.18,0.005) ""(4.18,0.005)
  oval 1.65x1.85 hole 1.75 slot 1.55 at 0 deg: ""(-2.502,-2.687) ""(2.494,-2.695)
  Keep-Out Layer board cut-out: 3.81,1.707 3.885,1.707 4.032,1.736 4.171,1.794 4.296,1.877 4.402,1.983 4.485,2.108 4.543,2.247 4.572,2.394 4.572,2.469 4.572,2.544 4.543,2.691 4.485,2.83 4.402,2.955 4.296,3.061 4.171,3.144 4.032,3.202 3.885,3.231 3.81,3.231 3.81,3.231 -3.81,3.231 -3.885,3.231 -4.032,3.202 -4.171,3.144 -4.296,3.061 -4.402,2.955 -4.485,2.83 -4.543,2.691 -4.572,2.544 -4.572,2.469 -4.572,2.394 -4.543,2.247 -4.485,2.108 -4.402,1.983 -4.296,1.877 -4.171,1.794 -4.032,1.736 -3.885,1.707 -3.81,1.707 -3.81,1.707
  Keep-Out Layer board cut-out: 3.81,1.707 3.885,1.707 4.032,1.736 4.171,1.794 4.296,1.877 4.402,1.983 4.485,2.108 4.543,2.247 4.572,2.394 4.572,2.469 4.572,2.544 4.543,2.691 4.485,2.83 4.402,2.955 4.296,3.061 4.171,3.144 4.032,3.202 3.885,3.231 3.81,3.231 3.81,3.231 -3.81,3.231 -3.885,3.231 -4.032,3.202 -4.171,3.144 -4.296,3.061 -4.402,2.955 -4.485,2.83 -4.543,2.691 -4.572,2.544 -4.572,2.469 -4.572,2.394 -4.543,2.247 -4.485,2.108 -4.402,1.983 -4.296,1.877 -4.171,1.794 -4.032,1.736 -3.885,1.707 -3.81,1.707 -3.81,1.707
  silkscreen extent -4.22,-3.62 4.23,-1.06, body extent -4.02,-2.88 4.02,2.7, height 2.74

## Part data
C1 C7 C8 C10 C12 C13 C16 C18 C22 C26 C28 C30 C32 C36: library part CAP0012, "Capacitor", Manufacturer 1=Cal-Chip, Manufacturer 2=Panasonic, Manufacturer 3="NIC Components", Manufacturer 4=ROHM, Manufacturer 5=Murata, Manufacturer Part Number 1=GMC10Y5V104Z25NTLF, Manufacturer Part Number 2=ECJ-1VF1E104Z, Manufacturer Part Number 3=NMC0603Y5V104Z25TRPF, Manufacturer Part Number 4=MCH182FN104ZK, Manufacturer Part Number 5=GRM188F51E104ZA01D, Operating Temperature="-30C to + 85C", Package=0603, Temperature Coeffcient=Y5V, Tolerance=20%, Voltage=50V
C2 C3 C4 C5 C15 C19 C21: library part CAP1130, "Capacitor", Manufacturer 1=TDK, Manufacturer Part Number 1=C1608X7R1H333K, Operating Temperature="-55C to +125C", Package=0603, Supplier Part Number 1=445-5093-1-ND, Temperature Coeffcient=X7R, Tolerance=10%, Voltage=50V
C6: library part CAP0372, "Capacitor", Manufacturer 1="Taiyo Yuden", Manufacturer Part Number 1=LMK212BJ106KG-T, Manufacturer Part Number 2=LMK212BJ106KD-T, Operating Temperature="-55C to +85C", Package=0805, Supplier Part Number 1=587-1300-1-ND, Temperature Coeffcient=X5R, Tolerance=10%, Voltage=10V
C9: library part CAP1426, "Capacitor", Manufacturer 1="Johanson Dielectrics Inc", Manufacturer Part Number 1=501R18W223KV4E, Operating Temperature="-55C to +125C", Package=1206, Supplier Part Number 1=709-1028-1-ND, Tolerance=10%, Voltage=450V
C11: library part CAP0012, "Capacitor", Manufacturer 1=Cal-Chip, Manufacturer 2=Panasonic, Manufacturer 3="NIC Components", Manufacturer 4=ROHM, Manufacturer 5=Murata, Manufacturer Part Number 1=GMC10Y5V104Z25NTLF, Manufacturer Part Number 2=ECJ-1VF1E104Z, Manufacturer Part Number 3=NMC0603Y5V104Z25TRPF, Manufacturer Part Number 4=MCH182FN104ZK, Manufacturer Part Number 5=GRM188F51E104ZA01D, Operating Temperature="-30C to + 85C", Package=0603, Temperature Coeffcient=Y5V, Tolerance=20%, Voltage=25V
C14: library part CAP2158, "Capacitor", Manufacturer 1="TDK Corporation", Manufacturer Part Number 1=CGA4F4X7T2W103M085AE, Operating Temperature="-55C to +125C", Package=0805, Supplier Part Number 1=445-7966-1-ND, Temperature Coeffcient=X7T, Tolerance=10%, Voltage=450V
C17 C20: library part CAP1130, "Capacitor", Manufacturer 1=TDK, Manufacturer Part Number 1=C1608X7R1H333K, Operating Temperature="-55C to +125C", Package=0603, Supplier Part Number 1=445-5093-1-ND, Temperature Coeffcient=X7R, Tolerance=10%, Voltage=16V
C23: library part CAP0419, "Capacitor", Package=0805, Voltage=16V
C24: library part CAP1060, "Capacitor", Manufacturer 1="TDK Corporation", Manufacturer Part Number 1=CGA3E1X7R1E105K080AC, Manufacturer Part Number 2=C1608X7R1E105K, Operating Temperature="-55C to +125C", Package=0603, Supplier Part Number 1=445-6931-1-ND, Temperature Coeffcient=X7R, Tolerance=10%, Voltage=25V
C25: library part CAP0011, "Capacitor", Manufacturer 1="Wurth Electronics Inc", Manufacturer 2=Samsung, Manufacturer 3=AVX, Manufacturer 4=Murata, Manufacturer 5="Taiyo Yuden", Manufacturer 6=Panasonic, Manufacturer 7=Yageo, Manufacturer 8="NIC Components", Manufacturer Part Number 1=885012206046, Manufacturer Part Number 2=CL10B104KO8NNNC, Manufacturer Part Number 3=0603YC104KAT2A, Manufacturer Part Number 4=GRM188R71C104KA01D, Manufacturer Part Number 5=EMK107B7104KA-T, Manufacturer Part Number 6=ECJ-1VB1C104K, Manufacturer Part Number 7=CC0603KRX7R7BB104, Manufacturer Part Number 8=NMC0603X7R104K16TRPF, Operating Temperature="-55C to +125C", Package=0603, Supplier Part Number 1=732-7965-1-ND, Temperature Coeffcient=X7R, Tolerance=10%, Voltage=50V
C27: library part CAP1159, "Capacitor", Manufacturer 1="Murata Electronics North America", Manufacturer 2="Taiyo Yuden", Manufacturer Part Number 1=GRM31CR71E106KA12L, Manufacturer Part Number 2=TMK316B7106KL-TD, Operating Temperature="-55C to +125C", Package=1206, Supplier Part Number 1=490-6518-1-ND, Temperature Coeffcient=X7R, Tolerance=10%, Voltage=25V
C29 C31: library part CAP1979, "Capacitor", Manufacturer 1="TDK Corporation", Manufacturer Part Number 1=C2012X7R1A106K125AC, Operating Temperature="-55C to +125C", Package=0805, Supplier Part Number 1=445-6857-1-ND, Temperature Coeffcient=X7R, Tolerance=10%, Voltage=10V
C33: library part CAP1929, Manufacturer 1="TDK Corporation", Manufacturer Part Number 1=C5750X7T2W105M250KE, Operating Temperature="-55C to +125C", Package=2220, Supplier Part Number 1=445-6841-1-ND, Temperature Coeffcient=X7T, Tolerance=20%, Voltage=450V
C35: library part CAP1007, "Capacitor", Package=RAD-P2.5D6.3H11, Voltage=400V
C37: library part CAP1906, "Capacitor", Package=P5D10H20, Voltage=50V
D1: library part DIODE1422, Forward Current=0.3A, Manufacturer 1=Panasonic, Manufacturer Part Number 1=DA2JF2300L, Operating Temperature="-40C to +85C", Package=SC-90A, Reverse Current=1uA, Reverse Voltage=300V, Supplier Part Number 1=2284103
FB1 FB2 FB3 FB4: library part IND1114, Manufacturer 1=Laird, Manufacturer Part Number 1=LI0805H151R-10, Package=0805, Saturation Current=800mA, Supplier Part Number 1=240-2384-1-ND
J1: library part CON1105, Manufacturer 1=FCI, Manufacturer 2=Nextron, Manufacturer Part Number 1=68000-103HLF, Manufacturer Part Number 2=R-211-0311-0021-000, Supplier Part Number 1=609-3461-ND
J2 J3 J4 J5 J6 J13: library part CON1108, Manufacturer 1=FCI, Manufacturer 4=Samtec, Manufacturer 5=Sullins, Manufacturer 6="SPC Technology", Manufacturer 8=Nextron, Manufacturer Part Number 1=77311-118-02LF, Manufacturer Part Number 2=68001-202HLF, Manufacturer Part Number 3=68000-202HLF, Manufacturer Part Number 4=TSW-102-07-G-S, Manufacturer Part Number 5=PBC02SAAN, Manufacturer Part Number 6=SPC20481, Manufacturer Part Number 7=TSW-102-07-F-S, Manufacturer Part Number 8=R-211-0211-0021-000, Manufacturer Part Number 9=TSW-102-07-S-S, Supplier Part Number 1=609-4434-ND
J7 J10: library part CON0465, Manufacturer 1=Samtec, Manufacturer 2="SHENZHEN JUNHAO ENGINEERING", Manufacturer Part Number 1=TSW-103-07-T-S, Manufacturer Part Number 2=R-211-0311-0021-000, Supplier Part Number 1=SAM1035-03-ND
J8: Manufacturer 1=FCI, Manufacturer 2=YangMing, Manufacturer Part Number 1=10118194-0001LF, Manufacturer Part Number 2=YM-02-363-N05F, Supplier Part Number 1=609-4618-1-ND
J9: library part CON0148, Manufacturer 1="Wurth Electronics Inc", Manufacturer 2=Samtec, Manufacturer 3="SHENZHEN JUNHAO ENGINEERING", Manufacturer Part Number 1=61300411121, Manufacturer Part Number 2=TSW-104-07-G-S, Manufacturer Part Number 3=R-211-0411-0021-000, Supplier Part Number 1=732-5317-ND
J11: library part CON1626, Current=16A, Manufacturer 1="Wurth Electronics Inc.", Manufacturer Part Number 1=691137710003, Supplier Part Number 1=732-10956-ND, Value2=Inlet, Voltage=300V
J12: library part CON1626, Current=16A, Manufacturer 1="Wurth Electronics Inc.", Manufacturer Part Number 1=691137710003, Supplier Part Number 1=732-10956-ND, Value2=Outlet, Voltage=300V
L1: library part IND1323, Manufacturer 1="Wurth Electronics Inc", Manufacturer Part Number 1=7447412681, Operating Temperature="-40C to +125C", Package=P5D8.5H5.5, RMS Current=330mA, Saturation Current=350mA, Supplier Part Number 1=732-3733-ND, Test Frequency=1kHz
LABEL: library part 08-00028
LED1 LED2 LED3 LED4 LED5 LED7: library part DIODE1058, "LED", Forward Current=30mA, Manufacturer 1=Lite-On, Manufacturer 2=ZhiDing, Manufacturer Part Number 1=LTST-C190EKT, Manufacturer Part Number 2=AL-S0603SRC-50-08-2, Operating Temperature="-55C to +85C", Package=0603, Power=100mW, Reverse Current=100uA, Reverse Voltage=5V, Supplier Part Number 1=160-1182-1-ND
LED6: library part DIODE1243, "LED", Forward Current=20mA, Manufacturer 1="Stanley Electric Co                                                                               Stanley Electric Co", Manufacturer Part Number 1=PG1111C-TR, Package=0603, Supplier Part Number 1=404-1004-1-ND
MOV1: library part RES1452, Current=6kA, Manufacturer 1="EPCOS Inc", Manufacturer Part Number 1=S14K275E2K1, Operating Temperature="-40C to +85C", Package="DISC 14mm", Supplier Part Number 1=495-4291-ND, Voltage=275VAC
PAD1 PAD2 PAD3 PAD4: library part MISC1024, Manufacturer 1=3M, Manufacturer Part Number 1=SJ61A11, Supplier Part Number 1=SJ5747-0-ND
Q1: library part TRA1253, "Transistor MOS", Current=200mA, Drain to Source Voltage=600V, Gate to Source Voltage=20V, Manufacturer 1="Microchip Technology", Manufacturer Part Number 1=VN2460N8-G, Operating Temperature="-55C to +150C", Package=SOT-89, Power=1.6W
